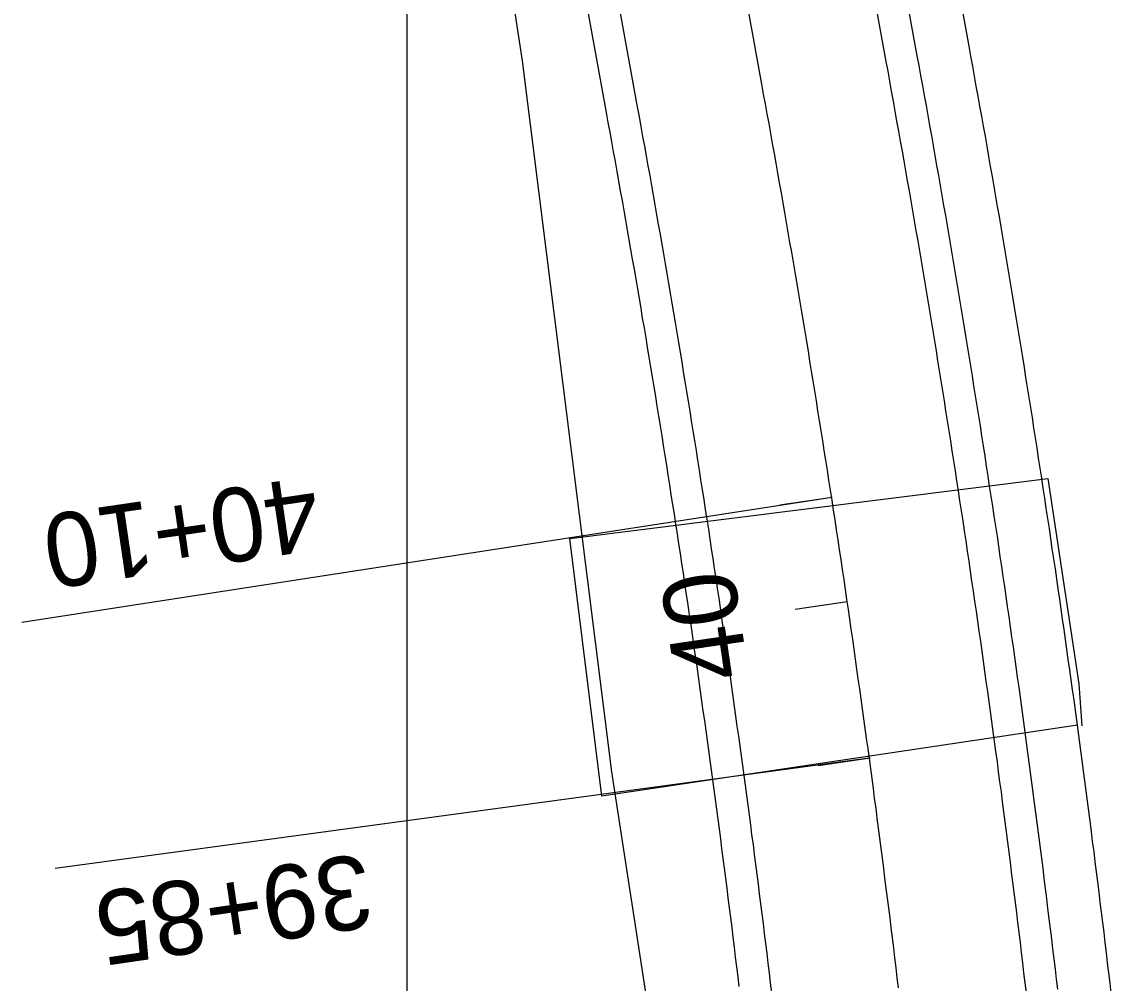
# Model space of a CAD drawing. Extents: x 2318076 to 2324211, y 613525 to 630327.
# Drawn here: x 2318843.9 to 2318947.3, y 618898.1 to 618989.3 of the extents above; entities that cross this region are included whole.
import ezdxf

# ---------------------------------------------------------------- set-up
doc = ezdxf.new("R2010")
doc.units = 0
for name, color, linetype in [('BR_X_Slab_Object', 7, 'Continuous'), ('GE_P_CL_50', 7, 'Continuous'), ('PV_P_EOP', 7, 'Continuous'), ('PV_P_Shoulder', 7, 'Continuous'), ('RD_X_GR_Lt', 7, 'Continuous'), ('RD_X_GR_Rt', 7, 'Continuous'), ('SC_Scratch3', 7, 'Continuous')]:
    doc.layers.add(name, color=color, linetype=linetype)

msp = doc.modelspace()

# ---------------------------------------------------------------- linework, layer by layer
at = {"layer": 'BR_X_Slab_Object'}
msp.add_lwpolyline([(2318944.1, 618922.54), (2318898.95, 618915.8), (2318895.92, 618940.26), (2318941.31, 618945.98), (2318944.25, 618926.48), (2318944.25, 618926.48), (2318944.52, 618922.5)], dxfattribs=at)
at = {"layer": 'GE_P_CL_50'}
for p, q in [((2318920.77, 618944.15), (2318843.86, 618932.3)), ((2318920.8, 618944.16), (2318915.86, 618943.43)), ((2318922.25, 618934.26), (2318917.3, 618933.54)), ((2318922.25, 618934.26), (2318917.3, 618933.54)), ((2318924.34, 618919.41), (2318847.03, 618908.93)), ((2318924.42, 618919.42), (2318919.48, 618918.7))]:
    msp.add_line(p, q, dxfattribs=at)
msp.add_lwpolyline([(2318927.11, 618897.63), (2318927, 618898.57), (2318926.89, 618899.52), (2318926.77, 618900.47), (2318926.66, 618901.41), (2318926.54, 618902.36), (2318926.43, 618903.31), (2318926.31, 618904.25), (2318926.19, 618905.2), (2318926.07, 618906.14), (2318925.95, 618907.09), (2318925.83, 618908.04), (2318925.71, 618908.98), (2318925.59, 618909.93), (2318925.47, 618910.87), (2318925.35, 618911.82), (2318925.23, 618912.77), (2318925.1, 618913.71), (2318924.98, 618914.66), (2318924.85, 618915.6), (2318924.73, 618916.55), (2318924.6, 618917.49), (2318924.48, 618918.44), (2318924.35, 618919.38), (2318924.22, 618920.33), (2318924.09, 618921.27), (2318923.96, 618922.22), (2318923.83, 618923.16), (2318923.7, 618924.1), (2318923.57, 618925.05), (2318923.44, 618925.99), (2318923.3, 618926.94), (2318923.17, 618927.88), (2318923.04, 618928.83), (2318922.9, 618929.77), (2318922.77, 618930.71), (2318922.63, 618931.66), (2318922.49, 618932.6), (2318922.36, 618933.54), (2318922.22, 618934.49), (2318922.08, 618935.43), (2318921.94, 618936.37), (2318921.8, 618937.32), (2318921.66, 618938.26), (2318921.52, 618939.2), (2318921.38, 618940.15), (2318921.23, 618941.09), (2318921.09, 618942.03), (2318920.95, 618942.97), (2318920.8, 618943.92), (2318920.66, 618944.86), (2318920.51, 618945.8), (2318920.36, 618946.74), (2318920.22, 618947.69), (2318920.07, 618948.63), (2318919.92, 618949.57), (2318919.77, 618950.51), (2318919.62, 618951.45), (2318919.47, 618952.39), (2318919.32, 618953.34), (2318919.17, 618954.28), (2318919.02, 618955.22), (2318918.86, 618956.16), (2318918.71, 618957.1), (2318918.56, 618958.04), (2318918.4, 618958.98), (2318918.24, 618959.92), (2318918.09, 618960.86), (2318917.93, 618961.8), (2318917.77, 618962.74), (2318917.62, 618963.68), (2318917.46, 618964.62), (2318917.3, 618965.56), (2318917.14, 618966.5), (2318916.98, 618967.44), (2318916.81, 618968.38), (2318916.65, 618969.32), (2318916.49, 618970.26), (2318916.33, 618971.2), (2318916.16, 618972.14), (2318916, 618973.08), (2318915.83, 618974.02), (2318915.66, 618974.96), (2318915.5, 618975.9), (2318915.33, 618976.83), (2318915.16, 618977.77), (2318914.99, 618978.71), (2318914.82, 618979.65), (2318914.65, 618980.59), (2318914.48, 618981.52), (2318914.31, 618982.46), (2318914.14, 618983.4), (2318905.18, 619032.79)], dxfattribs=at)
at = {"layer": 'PV_P_EOP'}
for points in [[(2318939.26, 618897.13), (2318939.14, 618898.09), (2318939.03, 618899.05), (2318938.92, 618900), (2318938.8, 618900.96), (2318938.69, 618901.91), (2318938.57, 618902.86), (2318938.45, 618903.82), (2318938.34, 618904.77), (2318938.22, 618905.73), (2318938.1, 618906.68), (2318937.98, 618907.64), (2318937.86, 618908.59), (2318937.74, 618909.55), (2318937.62, 618910.5), (2318937.5, 618911.45), (2318937.37, 618912.41), (2318937.25, 618913.36), (2318937.13, 618914.32), (2318937, 618915.27), (2318936.88, 618916.22), (2318936.75, 618917.18), (2318936.62, 618918.13), (2318936.5, 618919.08), (2318936.37, 618920.04), (2318936.24, 618920.99), (2318936.11, 618921.94), (2318935.98, 618922.9), (2318935.85, 618923.85), (2318935.72, 618924.8), (2318935.59, 618925.75), (2318935.45, 618926.71), (2318935.32, 618927.66), (2318935.19, 618928.61), (2318935.05, 618929.57), (2318934.92, 618930.52), (2318934.78, 618931.47), (2318934.64, 618932.42), (2318934.51, 618933.37), (2318934.37, 618934.33), (2318934.23, 618935.28), (2318934.09, 618936.23), (2318933.95, 618937.18), (2318933.81, 618938.13), (2318933.67, 618939.08), (2318933.53, 618940.04), (2318933.39, 618940.99), (2318933.24, 618941.94), (2318933.1, 618942.89), (2318932.95, 618943.84), (2318932.81, 618944.79), (2318932.66, 618945.74), (2318932.52, 618946.69), (2318932.37, 618947.64), (2318932.22, 618948.59), (2318932.07, 618949.54), (2318931.92, 618950.49), (2318931.77, 618951.44), (2318931.62, 618952.39), (2318931.47, 618953.34), (2318931.32, 618954.29), (2318931.17, 618955.24), (2318931.02, 618956.19), (2318930.86, 618957.14), (2318930.71, 618958.09), (2318930.55, 618959.04), (2318930.4, 618959.99), (2318930.24, 618960.94), (2318930.08, 618961.89), (2318929.93, 618962.84), (2318929.77, 618963.78), (2318929.61, 618964.73), (2318929.45, 618965.68), (2318929.29, 618966.63), (2318929.13, 618967.58), (2318928.97, 618968.53), (2318928.8, 618969.47), (2318928.64, 618970.42), (2318928.48, 618971.37), (2318928.31, 618972.32), (2318928.15, 618973.26), (2318927.98, 618974.21), (2318927.81, 618975.16), (2318927.65, 618976.11), (2318927.48, 618977.05), (2318927.31, 618978), (2318927.14, 618978.95), (2318926.97, 618979.89), (2318926.8, 618980.84), (2318926.63, 618981.79), (2318926.46, 618982.73), (2318926.29, 618983.68), (2318926.12, 618984.62), (2318925.95, 618985.55), (2318916.99, 619034.89)], [(2318915.09, 618897.15), (2318914.97, 618898.09), (2318914.86, 618899.02), (2318914.75, 618899.96), (2318914.63, 618900.9), (2318914.52, 618901.84), (2318914.4, 618902.78), (2318914.28, 618903.71), (2318914.17, 618904.65), (2318914.05, 618905.59), (2318913.93, 618906.53), (2318913.81, 618907.47), (2318913.69, 618908.4), (2318913.57, 618909.34), (2318913.45, 618910.28), (2318913.33, 618911.21), (2318913.2, 618912.15), (2318913.08, 618913.09), (2318912.96, 618914.03), (2318912.83, 618914.96), (2318912.71, 618915.9), (2318912.58, 618916.84), (2318912.46, 618917.77), (2318912.33, 618918.71), (2318912.2, 618919.65), (2318912.07, 618920.58), (2318911.94, 618921.52), (2318911.81, 618922.46), (2318911.68, 618923.39), (2318911.55, 618924.33), (2318911.42, 618925.26), (2318911.29, 618926.2), (2318911.16, 618927.13), (2318911.02, 618928.07), (2318910.89, 618929.01), (2318910.75, 618929.94), (2318910.62, 618930.88), (2318910.48, 618931.81), (2318910.35, 618932.75), (2318910.21, 618933.68), (2318910.07, 618934.62), (2318909.93, 618935.55), (2318909.79, 618936.49), (2318909.65, 618937.42), (2318909.51, 618938.36), (2318909.37, 618939.29), (2318909.23, 618940.23), (2318909.09, 618941.16), (2318908.94, 618942.09), (2318908.8, 618943.03), (2318908.65, 618943.96), (2318908.51, 618944.9), (2318908.36, 618945.83), (2318908.22, 618946.76), (2318908.07, 618947.7), (2318907.92, 618948.63), (2318907.77, 618949.56), (2318907.62, 618950.5), (2318907.47, 618951.43), (2318907.32, 618952.36), (2318907.17, 618953.3), (2318907.02, 618954.23), (2318906.87, 618955.16), (2318906.71, 618956.09), (2318906.56, 618957.03), (2318906.41, 618957.96), (2318906.25, 618958.89), (2318906.1, 618959.82), (2318905.94, 618960.76), (2318905.78, 618961.69), (2318905.63, 618962.62), (2318905.47, 618963.55), (2318905.31, 618964.48), (2318905.15, 618965.41), (2318904.99, 618966.35), (2318904.83, 618967.28), (2318904.67, 618968.21), (2318904.5, 618969.14), (2318904.34, 618970.07), (2318904.18, 618971), (2318904.01, 618971.93), (2318903.85, 618972.86), (2318903.68, 618973.79), (2318903.52, 618974.72), (2318903.35, 618975.65), (2318903.18, 618976.58), (2318903.02, 618977.51), (2318902.85, 618978.44), (2318902.68, 618979.37), (2318902.51, 618980.3), (2318902.33, 618981.25), (2318893.36, 619030.69)]]:
    msp.add_lwpolyline(points, dxfattribs=at)
at = {"layer": 'PV_P_Shoulder'}
for points in [[(2318942.23, 618897.49), (2318942.12, 618898.44), (2318942.01, 618899.4), (2318941.89, 618900.36), (2318941.78, 618901.31), (2318941.66, 618902.27), (2318941.55, 618903.23), (2318941.43, 618904.18), (2318941.31, 618905.14), (2318941.19, 618906.1), (2318941.08, 618907.05), (2318940.96, 618908.01), (2318940.84, 618908.97), (2318940.71, 618909.92), (2318940.59, 618910.88), (2318940.47, 618911.84), (2318940.35, 618912.79), (2318940.22, 618913.75), (2318940.1, 618914.7), (2318939.98, 618915.66), (2318939.85, 618916.62), (2318939.72, 618917.57), (2318939.6, 618918.53), (2318939.47, 618919.48), (2318939.34, 618920.44), (2318939.21, 618921.39), (2318939.08, 618922.35), (2318938.95, 618923.3), (2318938.82, 618924.26), (2318938.69, 618925.21), (2318938.56, 618926.17), (2318938.43, 618927.12), (2318938.29, 618928.08), (2318938.16, 618929.03), (2318938.02, 618929.99), (2318937.89, 618930.94), (2318937.75, 618931.89), (2318937.61, 618932.85), (2318937.48, 618933.8), (2318937.34, 618934.76), (2318937.2, 618935.71), (2318937.06, 618936.66), (2318936.92, 618937.62), (2318936.78, 618938.57), (2318936.64, 618939.53), (2318936.5, 618940.48), (2318936.35, 618941.43), (2318936.21, 618942.38), (2318936.06, 618943.34), (2318935.92, 618944.29), (2318935.77, 618945.24), (2318935.63, 618946.2), (2318935.48, 618947.15), (2318935.33, 618948.1), (2318935.19, 618949.05), (2318935.04, 618950.01), (2318934.89, 618950.96), (2318934.74, 618951.91), (2318934.59, 618952.86), (2318934.44, 618953.82), (2318934.28, 618954.77), (2318934.13, 618955.72), (2318933.98, 618956.67), (2318933.82, 618957.62), (2318933.67, 618958.57), (2318933.51, 618959.52), (2318933.36, 618960.48), (2318933.2, 618961.43), (2318933.04, 618962.38), (2318932.88, 618963.33), (2318932.73, 618964.28), (2318932.57, 618965.23), (2318932.41, 618966.18), (2318932.25, 618967.13), (2318932.08, 618968.08), (2318931.92, 618969.03), (2318931.76, 618969.98), (2318931.6, 618970.93), (2318931.43, 618971.88), (2318931.27, 618972.83), (2318931.1, 618973.78), (2318930.94, 618974.73), (2318930.77, 618975.68), (2318930.6, 618976.63), (2318930.43, 618977.58), (2318930.27, 618978.53), (2318930.1, 618979.47), (2318929.93, 618980.42), (2318929.76, 618981.37), (2318929.58, 618982.32), (2318929.41, 618983.27), (2318929.24, 618984.22), (2318929.07, 618985.16), (2318928.9, 618986.09), (2318919.94, 619035.42)], [(2318911.99, 618897.73), (2318911.88, 618898.66), (2318911.77, 618899.6), (2318911.65, 618900.54), (2318911.54, 618901.47), (2318911.42, 618902.41), (2318911.31, 618903.34), (2318911.19, 618904.28), (2318911.07, 618905.21), (2318910.95, 618906.15), (2318910.83, 618907.09), (2318910.71, 618908.02), (2318910.59, 618908.96), (2318910.47, 618909.89), (2318910.35, 618910.83), (2318910.23, 618911.76), (2318910.11, 618912.7), (2318909.98, 618913.63), (2318909.86, 618914.57), (2318909.73, 618915.5), (2318909.61, 618916.44), (2318909.48, 618917.37), (2318909.36, 618918.31), (2318909.23, 618919.24), (2318909.1, 618920.17), (2318908.97, 618921.11), (2318908.84, 618922.04), (2318908.71, 618922.98), (2318908.58, 618923.91), (2318908.45, 618924.84), (2318908.32, 618925.78), (2318908.19, 618926.71), (2318908.05, 618927.65), (2318907.92, 618928.58), (2318907.78, 618929.51), (2318907.65, 618930.45), (2318907.51, 618931.38), (2318907.38, 618932.31), (2318907.24, 618933.25), (2318907.1, 618934.18), (2318906.96, 618935.11), (2318906.82, 618936.04), (2318906.69, 618936.98), (2318906.54, 618937.91), (2318906.4, 618938.84), (2318906.26, 618939.77), (2318906.12, 618940.71), (2318905.98, 618941.64), (2318905.83, 618942.57), (2318905.69, 618943.5), (2318905.54, 618944.43), (2318905.4, 618945.37), (2318905.25, 618946.3), (2318905.11, 618947.23), (2318904.96, 618948.16), (2318904.81, 618949.09), (2318904.66, 618950.02), (2318904.51, 618950.95), (2318904.36, 618951.88), (2318904.21, 618952.82), (2318904.06, 618953.75), (2318903.91, 618954.68), (2318903.75, 618955.61), (2318903.6, 618956.54), (2318903.45, 618957.47), (2318903.29, 618958.4), (2318903.14, 618959.33), (2318902.98, 618960.26), (2318902.82, 618961.19), (2318902.67, 618962.12), (2318902.51, 618963.05), (2318902.35, 618963.98), (2318902.19, 618964.91), (2318902.03, 618965.84), (2318901.87, 618966.77), (2318901.71, 618967.69), (2318901.55, 618968.62), (2318901.39, 618969.55), (2318901.22, 618970.48), (2318901.06, 618971.41), (2318900.9, 618972.34), (2318900.73, 618973.27), (2318900.56, 618974.19), (2318900.4, 618975.12), (2318900.23, 618976.05), (2318900.06, 618976.98), (2318899.9, 618977.91), (2318899.73, 618978.83), (2318899.56, 618979.76), (2318899.38, 618980.71), (2318890.41, 619030.16)]]:
    msp.add_lwpolyline(points, dxfattribs=at)
at = {"layer": 'RD_X_GR_Lt'}
for p, q in [((2318891.42, 618985.61), (2318877.44, 619076.94)), ((2318899.88, 618918.12), (2318891.42, 618985.61)), ((2318914.32, 618824.85), (2318899.88, 618918.12))]:
    msp.add_line(p, q, dxfattribs=at)
at = {"layer": 'RD_X_GR_Rt'}
msp.add_lwpolyline([(2318947.31, 618897.11), (2318947.2, 618898.07), (2318947.09, 618899.03), (2318946.97, 618899.99), (2318946.86, 618900.95), (2318946.74, 618901.91), (2318946.63, 618902.87), (2318946.51, 618903.83), (2318946.39, 618904.79), (2318946.28, 618905.75), (2318946.16, 618906.71), (2318946.04, 618907.67), (2318945.92, 618908.63), (2318945.8, 618909.59), (2318945.68, 618910.55), (2318945.55, 618911.51), (2318945.43, 618912.47), (2318945.31, 618913.43), (2318945.18, 618914.39), (2318945.06, 618915.35), (2318944.93, 618916.31), (2318944.81, 618917.27), (2318944.68, 618918.23), (2318944.55, 618919.19), (2318944.43, 618920.15), (2318944.3, 618921.1), (2318944.17, 618922.06), (2318944.04, 618923.02), (2318943.91, 618923.98), (2318943.78, 618924.94), (2318943.64, 618925.9), (2318943.51, 618926.85), (2318943.38, 618927.81), (2318943.24, 618928.77), (2318943.11, 618929.73), (2318942.97, 618930.69), (2318942.84, 618931.64), (2318942.7, 618932.6), (2318942.56, 618933.56), (2318942.43, 618934.52), (2318942.29, 618935.48), (2318942.15, 618936.43), (2318942.01, 618937.39), (2318941.87, 618938.35), (2318941.72, 618939.3), (2318941.58, 618940.26), (2318941.44, 618941.22), (2318941.3, 618942.17), (2318941.15, 618943.13), (2318941.01, 618944.09), (2318940.86, 618945.04), (2318940.72, 618946), (2318940.57, 618946.96), (2318940.42, 618947.91), (2318940.27, 618948.87), (2318940.13, 618949.82), (2318939.98, 618950.78), (2318939.83, 618951.74), (2318939.68, 618952.69), (2318939.52, 618953.65), (2318939.37, 618954.6), (2318939.22, 618955.56), (2318939.07, 618956.51), (2318938.91, 618957.47), (2318938.76, 618958.42), (2318938.6, 618959.38), (2318938.45, 618960.33), (2318938.29, 618961.29), (2318938.13, 618962.24), (2318937.98, 618963.2), (2318937.82, 618964.15), (2318937.66, 618965.1), (2318937.5, 618966.06), (2318937.34, 618967.01), (2318937.18, 618967.97), (2318937.01, 618968.92), (2318936.85, 618969.87), (2318936.69, 618970.83), (2318936.52, 618971.78), (2318936.36, 618972.73), (2318936.19, 618973.69), (2318936.03, 618974.64), (2318935.86, 618975.59), (2318935.69, 618976.54), (2318935.53, 618977.5), (2318935.36, 618978.45), (2318935.19, 618979.4), (2318935.02, 618980.35), (2318934.85, 618981.31), (2318934.68, 618982.26), (2318934.5, 618983.21), (2318934.33, 618984.16), (2318934.16, 618985.11), (2318933.98, 618986.06), (2318933.82, 618986.99), (2318924.87, 619036.29)], dxfattribs=at)
at = {"layer": 'SC_Scratch3'}
msp.add_line((2318880.45, 614778.41), (2318880.45, 630327.22), dxfattribs=at)

# ---------------------------------------------------------------- texts
at = {"layer": 'GE_P_CL_50'}
for s, rotation, p in [('40+10', 188.3217, (2318871.55, 618946.19)), ('40', 98.3217, (2318912.91, 618927.26)), ('39+85', 188.3217, (2318876.51, 618910.4))]:
    msp.add_text(s, height=7, rotation=rotation, dxfattribs=at).set_placement(p)

doc.saveas('drawing.dxf')
